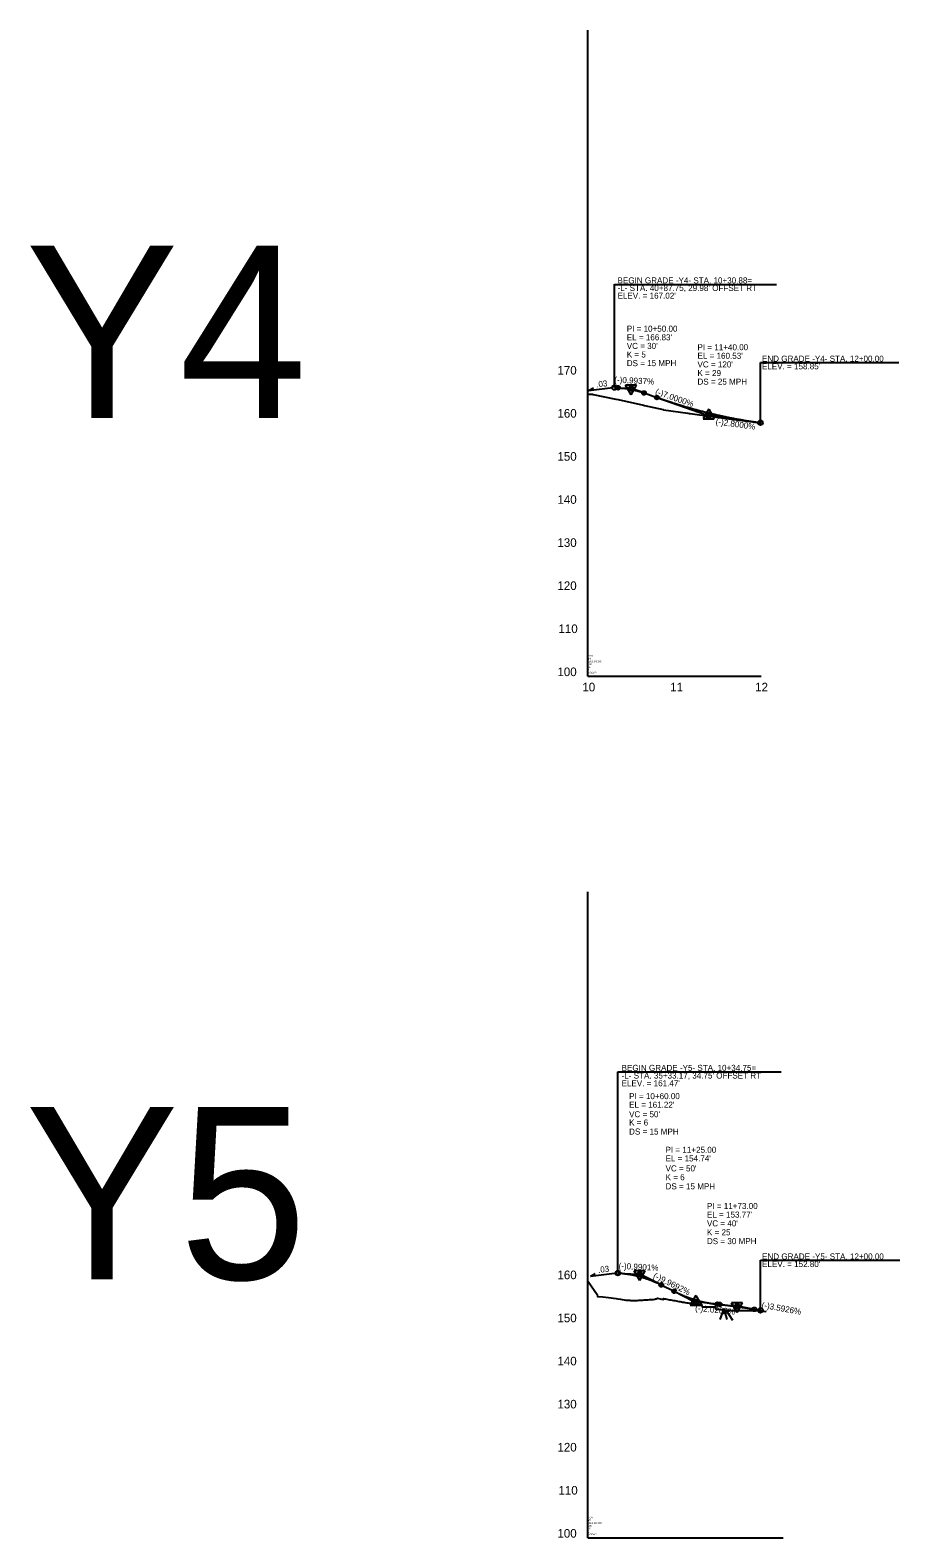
# Model space of a CAD drawing. Extents: x 1778432 to 1784301, y 601022 to 621789.
# Drawn here: x 1779496 to 1780505, y 612039 to 613789 of the extents above; entities that cross this region are included whole.
import ezdxf

# ---------------------------------------------------------------- set-up
doc = ezdxf.new("R2010")
doc.units = 0
for name, color, linetype in [('Exist Profile Cell', 7, 'Continuous'), ('Exist Vertical Profile Ground Line', 7, 'Continuous'), ('Exist Vertical Profile Horizontal Axis Label Major', 7, 'Continuous'), ('Exist Vertical Profile Vertical Axis Label', 7, 'Continuous'), ('Prop PFL Text', 7, 'Continuous'), ('Prop PFL VPI Symbol CELL', 7, 'Continuous'), ('Prop Vertical Profile Curve Label', 7, 'Continuous'), ('Prop Vertical Profile Grade', 7, 'Continuous'), ('Prop Vertical Profile Grade Label', 7, 'Continuous'), ('Prop VPI Label', 7, 'Continuous'), ('Scratch_Level_1', 7, 'Continuous')]:
    doc.layers.add(name, color=color, linetype=linetype)

msp = doc.modelspace()

# ---------------------------------------------------------------- linework, layer by layer
at = {"layer": 'Exist Profile Cell'}
for p, q in [((1780143, 613039.2), (1780143, 613789.2)), ((1780143, 613039.2), (1780343.8, 613039.2)), ((1780143, 613039.2), (1780143, 613039.2)), ((1780143, 612039.2), (1780143, 612789.2)), ((1780143, 612039.2), (1780369.4, 612039.2)), ((1780143, 612039.2), (1780143, 612039.2))]:
    msp.add_line(p, q, dxfattribs=at)
at = {"layer": 'Exist Vertical Profile Ground Line'}
for points in [[(1780143, 613366.4), (1780144.2, 613366.6), (1780145, 613366.6), (1780145.5, 613366.6), (1780146.7, 613366.6), (1780148.2, 613366.6), (1780148.9, 613366.4), (1780175.4, 613361), (1780178, 613360.5), (1780207.6, 613353.8), (1780208.7, 613353.6), (1780230.4, 613348.7), (1780230.8, 613348.6), (1780258.8, 613344.6), (1780260.4, 613344.3), (1780260.8, 613344.3), (1780261.4, 613344.2), (1780288.9, 613340.2), (1780318.1, 613336.6), (1780318.7, 613336.5), (1780339.8, 613333.9), (1780343.6, 613333.4)], [(1780143, 612337.1), (1780143.3, 612336.7), (1780153.5, 612321.5), (1780154, 612319.5), (1780160.2, 612318.8), (1780166.9, 612318.3), (1780175.6, 612316.9), (1780177.8, 612316.6), (1780180.6, 612316.2), (1780187.1, 612315), (1780191.6, 612314.9), (1780192.9, 612314.8), (1780194.4, 612314.8), (1780196, 612314.8), (1780197.5, 612314.8), (1780199, 612314.8), (1780199.5, 612314.8), (1780200.6, 612314.8), (1780202.1, 612314.9), (1780203.7, 612315), (1780205.2, 612315.1), (1780206.7, 612315.2), (1780208.3, 612315.3), (1780209.8, 612315.4), (1780211.3, 612315.5), (1780212.9, 612315.6), (1780214.4, 612315.7), (1780216, 612315.8), (1780216.3, 612315.8), (1780217.5, 612315.8), (1780218.3, 612315.8), (1780218.6, 612315.9), (1780219, 612316), (1780220.6, 612316.4), (1780221.5, 612316.6), (1780222.1, 612316.8), (1780223.7, 612317.2), (1780225.2, 612316.9), (1780226.7, 612316.6), (1780228.3, 612316.4), (1780229.8, 612316.1), (1780230.5, 612316), (1780230.8, 612316.9), (1780231.3, 612316.8), (1780232.9, 612316.5), (1780234.4, 612316.2), (1780235.9, 612315.9), (1780237.5, 612315.6), (1780239, 612315.3), (1780240.5, 612315), (1780242.1, 612314.7), (1780243.6, 612314.5), (1780245.2, 612314.2), (1780246.7, 612313.9), (1780248.2, 612313.7), (1780249.8, 612313.4), (1780251.3, 612313.1), (1780252.8, 612312.9), (1780254.4, 612312.6), (1780255.9, 612312.4), (1780257.5, 612312.1), (1780259, 612311.9), (1780260.5, 612311.7), (1780262.1, 612311.4), (1780263.6, 612311.2), (1780265.1, 612311), (1780266.7, 612310.7), (1780268.2, 612310.5), (1780269.8, 612310.3), (1780271.3, 612310.1), (1780272.8, 612309.9), (1780274.4, 612309.7), (1780274.8, 612309.6), (1780275.2, 612309.5), (1780275.4, 612307.3), (1780275.9, 612307.3), (1780277.1, 612307.3), (1780277.4, 612307.3), (1780279, 612307.3), (1780280.5, 612307.3), (1780282, 612307.2), (1780283.6, 612307.2), (1780285.1, 612307.2), (1780286.7, 612307.2), (1780287.3, 612307.2), (1780288.2, 612307.2), (1780289.7, 612307.2), (1780290.2, 612307.2), (1780290.9, 612305.1), (1780291.3, 612305), (1780292.2, 612304.8), (1780292.8, 612304.7), (1780293.2, 612304.7), (1780294.3, 612304.5), (1780295.9, 612304.3), (1780297.4, 612304.1), (1780299, 612303.9), (1780300.5, 612303.7), (1780301.7, 612303.5), (1780302, 612303.4), (1780303.6, 612303.4), (1780305.1, 612303.4), (1780306.6, 612303.3), (1780308.2, 612303.3), (1780309.7, 612303.2), (1780311.3, 612303.2), (1780312.8, 612303.2), (1780314.3, 612303.1), (1780315.9, 612303.1), (1780317.4, 612303.1), (1780318.9, 612303), (1780320.5, 612303), (1780322, 612302.9), (1780322.7, 612302.9), (1780323.5, 612302.9), (1780324.1, 612302.9), (1780324.7, 612302.9), (1780325.1, 612302.9), (1780325.5, 612302.9), (1780326.6, 612302.9), (1780328.2, 612302.9), (1780329.7, 612303), (1780331.2, 612303), (1780332.8, 612303), (1780334.3, 612303.1), (1780335.8, 612303.1), (1780337.4, 612303.1), (1780338.9, 612303.2), (1780340.5, 612303.2), (1780342.1, 612303.3), (1780342.7, 612303.2), (1780349.2, 612302.1), (1780349.8, 612302.4)]]:
    msp.add_lwpolyline(points, dxfattribs=at)
at = {"layer": 'Prop PFL VPI Symbol CELL'}
for p, q in [((1780193, 613365.9), (1780186.5, 613377.1)), ((1780199.4, 613377.1), (1780186.5, 613377.1)), ((1780193, 613365.9), (1780199.4, 613377.1)), ((1780283, 613349.3), (1780276.5, 613338.1)), ((1780283, 613349.3), (1780289.5, 613338.1)), ((1780276.5, 613338.1), (1780289.5, 613338.1)), ((1780203, 612337.8), (1780196.5, 612349)), ((1780209.4, 612349), (1780196.5, 612349)), ((1780203, 612337.8), (1780209.4, 612349)), ((1780268, 612320.4), (1780261.5, 612309.2)), ((1780261.5, 612309.2), (1780274.5, 612309.2)), ((1780268, 612320.4), (1780274.5, 612309.2)), ((1780316, 612300.6), (1780309.5, 612311.8)), ((1780322.4, 612311.8), (1780309.5, 612311.8)), ((1780316, 612300.6), (1780322.4, 612311.8))]:
    msp.add_line(p, q, dxfattribs=at)
for centre, radius in [((1780193, 613373.3), 1.75), ((1780193, 613373.3), 1.2), ((1780283, 613341.8), 1.75), ((1780283, 613341.8), 1.2), ((1780203, 612345.3), 1.75), ((1780203, 612345.3), 1.2), ((1780268, 612312.9), 1.75), ((1780268, 612312.9), 1.2), ((1780316, 612308), 1.75), ((1780316, 612308), 1.2)]:
    msp.add_circle(centre, radius, dxfattribs=at)
at = {"layer": 'Prop Vertical Profile Curve Label'}
for centre in [(1780178, 613374.1), (1780208, 613368.1), (1780223, 613362.8), (1780343, 613333.5), (1780178, 612346.5), (1780228, 612332.8), (1780243, 612325.4), (1780293, 612310.4), (1780296, 612310.1), (1780336, 612304.4)]:
    msp.add_circle(centre, 2.25, dxfattribs=at)
at = {"layer": 'Prop Vertical Profile Grade'}
for p, q in [((1780173.8, 613374.3), (1780178, 613374.1)), ((1780208, 613368.1), (1780223, 613362.8)), ((1780177.7, 612346.5), (1780178, 612346.5)), ((1780228, 612332.8), (1780243, 612325.4)), ((1780293, 612310.4), (1780296, 612310.1)), ((1780336, 612304.4), (1780343, 612303.2))]:
    msp.add_line(p, q, dxfattribs=at)
for points in [[(1780178, 613374.1), (1780178.6, 613374.1), (1780179.2, 613374), (1780179.8, 613374), (1780180.4, 613373.9), (1780181, 613373.9), (1780181.6, 613373.8), (1780182.2, 613373.8), (1780182.8, 613373.7), (1780183.4, 613373.7), (1780184, 613373.6), (1780184.6, 613373.5), (1780185.2, 613373.5), (1780185.8, 613373.4), (1780186.4, 613373.3), (1780187, 613373.2), (1780187.6, 613373.1), (1780188.2, 613373.1), (1780188.8, 613373), (1780189.4, 613372.9), (1780190, 613372.8), (1780190.6, 613372.7), (1780191.2, 613372.6), (1780191.8, 613372.4), (1780192.4, 613372.3), (1780193, 613372.2), (1780193.6, 613372.1), (1780194.2, 613372), (1780194.8, 613371.8), (1780195.4, 613371.7), (1780196, 613371.6), (1780196.6, 613371.4), (1780197.2, 613371.3), (1780197.8, 613371.1), (1780198.4, 613371), (1780199, 613370.8), (1780199.6, 613370.7), (1780200.2, 613370.5), (1780200.8, 613370.3), (1780201.4, 613370.2), (1780202, 613370), (1780202.6, 613369.8), (1780203.2, 613369.7), (1780203.8, 613369.5), (1780204.4, 613369.3), (1780205, 613369.1), (1780205.6, 613368.9), (1780206.2, 613368.7), (1780206.8, 613368.5), (1780207.4, 613368.3), (1780208, 613368.1)], [(1780223, 613362.8), (1780225.4, 613362), (1780227.8, 613361.2), (1780230.2, 613360.4), (1780232.6, 613359.6), (1780235, 613358.8), (1780237.4, 613358), (1780239.8, 613357.2), (1780242.2, 613356.4), (1780244.6, 613355.7), (1780247, 613354.9), (1780249.4, 613354.2), (1780251.8, 613353.5), (1780254.2, 613352.8), (1780256.6, 613352.1), (1780259, 613351.4), (1780261.4, 613350.7), (1780263.8, 613350), (1780266.2, 613349.4), (1780268.6, 613348.7), (1780271, 613348.1), (1780273.4, 613347.4), (1780275.8, 613346.8), (1780278.2, 613346.2), (1780280.6, 613345.6), (1780283, 613345), (1780285.4, 613344.4), (1780287.8, 613343.8), (1780290.2, 613343.3), (1780292.6, 613342.7), (1780295, 613342.2), (1780297.4, 613341.6), (1780299.8, 613341.1), (1780302.2, 613340.6), (1780304.6, 613340.1), (1780307, 613339.6), (1780309.4, 613339.1), (1780311.8, 613338.7), (1780314.2, 613338.2), (1780316.6, 613337.8), (1780319, 613337.3), (1780321.4, 613336.9), (1780323.8, 613336.5), (1780326.2, 613336), (1780328.6, 613335.6), (1780331, 613335.3), (1780333.4, 613334.9), (1780335.8, 613334.5), (1780338.2, 613334.1), (1780340.6, 613333.8), (1780343, 613333.5)], [(1780178, 612346.5), (1780179, 612346.5), (1780180, 612346.4), (1780181, 612346.3), (1780182, 612346.3), (1780183, 612346.2), (1780184, 612346.1), (1780185, 612346), (1780186, 612345.8), (1780187, 612345.7), (1780188, 612345.6), (1780189, 612345.4), (1780190, 612345.3), (1780191, 612345.1), (1780192, 612345), (1780193, 612344.8), (1780194, 612344.6), (1780195, 612344.4), (1780196, 612344.2), (1780197, 612344), (1780198, 612343.7), (1780199, 612343.5), (1780200, 612343.3), (1780201, 612343), (1780202, 612342.8), (1780203, 612342.5), (1780204, 612342.2), (1780205, 612341.9), (1780206, 612341.6), (1780207, 612341.3), (1780208, 612341), (1780209, 612340.7), (1780210, 612340.3), (1780211, 612340), (1780212, 612339.7), (1780213, 612339.3), (1780214, 612338.9), (1780215, 612338.6), (1780216, 612338.2), (1780217, 612337.8), (1780218, 612337.4), (1780219, 612337), (1780220, 612336.5), (1780221, 612336.1), (1780222, 612335.7), (1780223, 612335.2), (1780224, 612334.8), (1780225, 612334.3), (1780226, 612333.8), (1780227, 612333.3), (1780228, 612332.8)], [(1780243, 612325.4), (1780244, 612324.9), (1780245, 612324.4), (1780246, 612323.9), (1780247, 612323.4), (1780248, 612323), (1780249, 612322.5), (1780250, 612322.1), (1780251, 612321.6), (1780252, 612321.2), (1780253, 612320.8), (1780254, 612320.4), (1780255, 612319.9), (1780256, 612319.5), (1780257, 612319.2), (1780258, 612318.8), (1780259, 612318.4), (1780260, 612318), (1780261, 612317.7), (1780262, 612317.3), (1780263, 612317), (1780264, 612316.6), (1780265, 612316.3), (1780266, 612316), (1780267, 612315.7), (1780268, 612315.4), (1780269, 612315.1), (1780270, 612314.8), (1780271, 612314.5), (1780272, 612314.2), (1780273, 612314), (1780274, 612313.7), (1780275, 612313.5), (1780276, 612313.2), (1780277, 612313), (1780278, 612312.8), (1780279, 612312.6), (1780280, 612312.4), (1780281, 612312.2), (1780282, 612312), (1780283, 612311.8), (1780284, 612311.6), (1780285, 612311.4), (1780286, 612311.3), (1780287, 612311.1), (1780288, 612311), (1780289, 612310.8), (1780290, 612310.7), (1780291, 612310.6), (1780292, 612310.5), (1780293, 612310.4)], [(1780296, 612310.1), (1780296.8, 612310), (1780297.6, 612309.9), (1780298.4, 612309.8), (1780299.2, 612309.7), (1780300, 612309.6), (1780300.8, 612309.6), (1780301.6, 612309.5), (1780302.4, 612309.4), (1780303.2, 612309.3), (1780304, 612309.2), (1780304.8, 612309.1), (1780305.6, 612309), (1780306.4, 612308.9), (1780307.2, 612308.8), (1780308, 612308.7), (1780308.8, 612308.6), (1780309.6, 612308.5), (1780310.4, 612308.4), (1780311.2, 612308.3), (1780312, 612308.2), (1780312.8, 612308.1), (1780313.6, 612308), (1780314.4, 612307.9), (1780315.2, 612307.8), (1780316, 612307.6), (1780316.8, 612307.5), (1780317.6, 612307.4), (1780318.4, 612307.3), (1780319.2, 612307.2), (1780320, 612307.1), (1780320.8, 612307), (1780321.6, 612306.8), (1780322.4, 612306.7), (1780323.2, 612306.6), (1780324, 612306.5), (1780324.8, 612306.3), (1780325.6, 612306.2), (1780326.4, 612306.1), (1780327.2, 612306), (1780328, 612305.8), (1780328.8, 612305.7), (1780329.6, 612305.6), (1780330.4, 612305.4), (1780331.2, 612305.3), (1780332, 612305.2), (1780332.8, 612305), (1780333.6, 612304.9), (1780334.4, 612304.7), (1780335.2, 612304.6), (1780336, 612304.4)]]:
    msp.add_spline(points, degree=3, dxfattribs=at)
at = {"layer": 'Prop VPI Label'}
for p, q in [((1780173.8, 613374.3), (1780173.8, 613494.2)), ((1780173.8, 613494.1), (1780361.7, 613494.1)), ((1780343, 613333.5), (1780343, 613403.5)), ((1780343, 613403.5), (1780503.5, 613403.5)), ((1780143.7, 613370.8), (1780171.7, 613374.3)), ((1780143.7, 613370.8), (1780149.5, 613373.9)), ((1780178, 613374.1), (1780190.2, 613373.5)), ((1780208, 613368.1), (1780195.6, 613372.4)), ((1780223, 613362.8), (1780280.4, 613342.7)), ((1780343, 613333.5), (1780285.7, 613341.5)), ((1780177.7, 612349.3), (1780177.7, 612580.1)), ((1780177.7, 612580.1), (1780367.2, 612580.1)), ((1780343, 612303.2), (1780343, 612361.5)), ((1780343, 612361.5), (1780504.7, 612361.5)), ((1780145.8, 612343), (1780173.8, 612346.5)), ((1780145.8, 612343), (1780151.5, 612346.1)), ((1780178, 612346.5), (1780200.2, 612345.4)), ((1780228, 612332.8), (1780205.4, 612344.1)), ((1780243, 612325.4), (1780265.5, 612314.1)), ((1780293, 612310.4), (1780270.7, 612312.6)), ((1780296, 612310.1), (1780313.2, 612308.3)), ((1780336, 612304.4), (1780318.7, 612307.6))]:
    msp.add_line(p, q, dxfattribs=at)
for centre in [(1780173.8, 613374.3), (1780193, 613373.3), (1780283, 613341.8), (1780343, 613333.5), (1780177.7, 612346.5), (1780203, 612345.3), (1780268, 612312.9), (1780316, 612308), (1780343, 612303.2)]:
    msp.add_circle(centre, 2.75, dxfattribs=at)
at = {"layer": 'Scratch_Level_1'}
for p, q in [((1780300.4, 612305.3), (1780296.1, 612292.8)), ((1780300.4, 612304.5), (1780299.8, 612299)), ((1780300.4, 612305.3), (1780304.1, 612292.6)), ((1780303.7, 612302.8), (1780310.7, 612292))]:
    msp.add_line(p, q, dxfattribs=at)

# ---------------------------------------------------------------- texts
at = {"layer": 'Exist Profile Cell'}
for s, p in [('Y4', (1780143, 613058.7)), ('RDY', (1780143, 613061.9)), ('2', (1780143, 613045.7)), ('1000.000000', (1780143, 613055.4)), ('100', (1780143, 613052.2)), ('10', (1780143, 613048.9)), ('NOGAP', (1780143, 613042.4)), ('RDY', (1780143, 612061.9)), ('Y5', (1780143, 612058.7)), ('2', (1780143, 612045.7)), ('1000.000000', (1780143, 612055.4)), ('100', (1780143, 612052.2)), ('10', (1780143, 612048.9)), ('NOGAP', (1780143, 612042.4))]:
    msp.add_text(s, height=2, dxfattribs=at).set_placement(p)
at = {"layer": 'Exist Vertical Profile Horizontal Axis Label Major'}
for s, p in [('10', (1780136.5, 613021.7)), ('11', (1780238.4, 613021.7)), ('12', (1780336.9, 613021.7))]:
    msp.add_text(s, height=10, dxfattribs=at).set_placement(p)
at = {"layer": 'Exist Vertical Profile Vertical Axis Label'}
for s, p in [('170', (1780107.6, 613389.4)), ('160', (1780107.6, 613339.4)), ('150', (1780107.6, 613289.4)), ('140', (1780107.6, 613239.4)), ('130', (1780107.6, 613189.4)), ('120', (1780107.6, 613139.4)), ('110', (1780108.8, 613089.4)), ('100', (1780107.6, 613039.4)), ('160', (1780107.6, 612339.4)), ('160', (1780107.6, 612339.4)), ('150', (1780107.6, 612289.4)), ('150', (1780107.6, 612289.4)), ('140', (1780107.6, 612239.4)), ('140', (1780107.6, 612239.4)), ('130', (1780107.6, 612189.4)), ('130', (1780107.6, 612189.4)), ('120', (1780107.6, 612139.4)), ('120', (1780107.6, 612139.4)), ('110', (1780108.8, 612089.4)), ('110', (1780108.8, 612089.4)), ('100', (1780107.6, 612039.4)), ('100', (1780107.6, 612039.4))]:
    msp.add_text(s, height=10, dxfattribs=at).set_placement(p)
at = {"layer": 'Prop PFL Text'}
for s, p in [('Y4', (1779490.2, 613339.2)), ('Y5', (1779490.2, 612339.2))]:
    msp.add_text(s, height=200, dxfattribs=at).set_placement(p)
at = {"layer": 'Prop Vertical Profile Curve Label'}
for s, p in [("VC = 30'", (1780188, 613419.2)), ('K = 5', (1780188, 613409.2)), ('DS = 15 MPH', (1780188, 613399.2)), ("VC = 120'", (1780270, 613397.7)), ('K = 29', (1780270, 613387.7)), ('DS = 25 MPH', (1780270, 613377.7)), ('DS = 15 MPH', (1780190.7, 612507.3))]:
    msp.add_text(s, height=7, dxfattribs=at).set_placement(p)
at = {"layer": 'Prop Vertical Profile Grade Label'}
for s, rotation, p in [('.03', 7.125, (1780153, 613374.3)), ('(-)0.9937%', 357.1376, (1780173.4, 613380.1)), ('(-)7.0000%', 340.71, (1780220.4, 613366.8)), ('(-)2.8000%', 352.0477, (1780290.8, 613331.7)), ('.03', 7.125, (1780155.1, 612346.6)), ('(-)0.9901%', 357.1659, (1780178.4, 612351.4)), ('(-)9.9692%', 333.5055, (1780218, 612341.2)), ('(-)2.0208%', 354.2303, (1780267.1, 612302.7)), ('(-)3.5926%', 349.8166, (1780344, 612306.3))]:
    msp.add_text(s, height=7, rotation=rotation, dxfattribs=at).set_placement(p)
at = {"layer": 'Prop VPI Label'}
for s, p in [('BEGIN GRADE -Y4- STA. 10+30.88=', (1780177.3, 613495.2)), ("-L- STA. 40+87.75, 29.98' OFFSET RT", (1780177.3, 613486.4)), ("ELEV. = 167.02'", (1780177.3, 613477.5)), ('PI = 10+50.00', (1780188, 613439.2)), ("EL = 166.83'", (1780188, 613429.2)), ('PI = 11+40.00', (1780270, 613417.7)), ("EL = 160.53'", (1780270, 613407.7)), ('END GRADE -Y4- STA. 12+00.00', (1780344.8, 613404.4)), ("ELEV. = 158.85'", (1780344.8, 613395.5)), ('BEGIN GRADE -Y5- STA. 10+34.75=', (1780182, 612581.2)), ("-L- STA. 35+33.17, 34.75' OFFSET RT", (1780182, 612572.3)), ("ELEV. = 161.47'", (1780182, 612563.4)), ('PI = 10+60.00', (1780190.7, 612548.4)), ("EL = 161.22'", (1780190.7, 612538.4)), ("VC = 50'", (1780190.7, 612527.4)), ('K = 6', (1780190.7, 612517.8)), ('PI = 11+25.00', (1780233, 612486.1)), ("EL = 154.74'", (1780233, 612476.1)), ("VC = 50'", (1780233, 612464.5)), ('K = 6', (1780233, 612454.3)), ('DS = 15 MPH', (1780233, 612443.7)), ('PI = 11+73.00', (1780281, 612420.9)), ("EL = 153.77'", (1780281, 612410.9)), ("VC = 40'", (1780281, 612400.7)), ('K = 25', (1780281, 612390.4)), ('DS = 30 MPH', (1780281, 612380.1)), ('END GRADE -Y5- STA. 12+00.00', (1780344.9, 612362.3)), ("ELEV. = 152.80'", (1780344.9, 612353.5))]:
    msp.add_text(s, height=7, dxfattribs=at).set_placement(p)

doc.saveas('drawing.dxf')
